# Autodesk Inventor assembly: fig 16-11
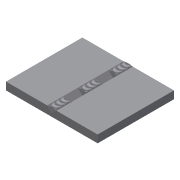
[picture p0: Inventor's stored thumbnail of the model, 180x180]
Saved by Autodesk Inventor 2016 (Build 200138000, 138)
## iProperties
Created: 2005-03
Part Number: fig 16-11
Document SubType Name: Weldment
Designer: CADCIM
Manufacturer: Standard
Standards Organization: Custom
Author: CADCIM
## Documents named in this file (2)
- D:\KAVITA\Autodesk Inventor_ 2016 Project_Kavita\Inventor_Part Files\Inventor_2016_Part\c16_Inv_2016\c16_inv_2016_prt\fig 16-11\fig 16-11.iam
- D:\KAVITA\Autodesk Inventor_ 2016 Project_Kavita\Inventor_Part Files\Inventor_2016_Part\c16_Inv_2016\c16_inv_2016_prt\fig 16-11\Part1.ipt
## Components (2 placed, 1 different names)
1. Part1:1 — Mate:1, Flush:1, Flush:2
2. Part1:2 — Mate:1, Flush:1, Flush:2
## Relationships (3: Flush 2, Mate 1)
- Mate:1: Part1:1 ↔ Part1:2
- Flush:1: Part1:1 ↔ Part1:2
- Flush:2: Part1:1 ↔ Part1:2
